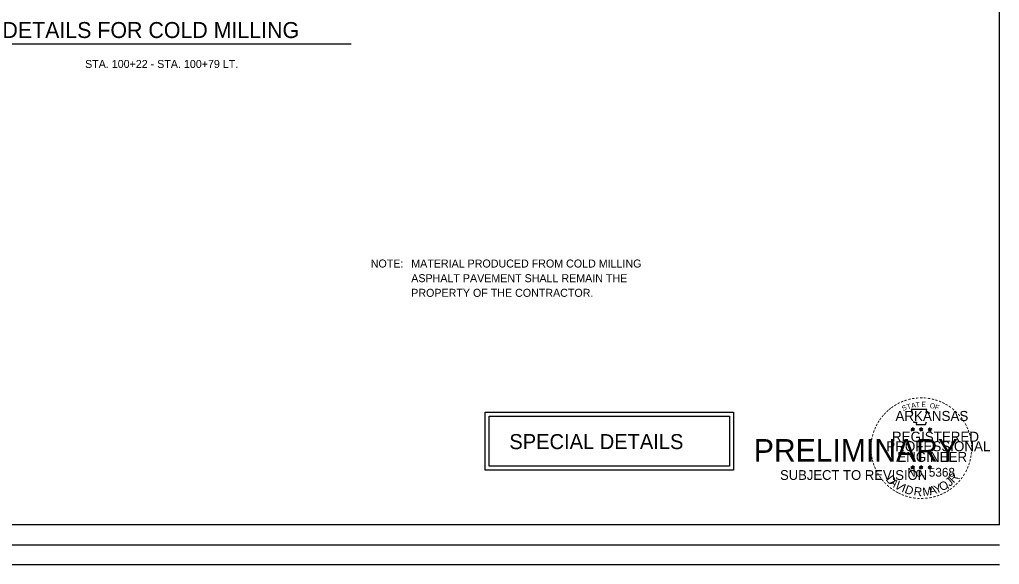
# Model space of a CAD drawing. Extents: x 1944905 to 1956777, y 763871 to 764977.
# Drawn here: x 1954088 to 1955068, y 763871 to 764415 of the extents above; entities that cross this region are included whole.
import ezdxf

# ---------------------------------------------------------------- set-up
doc = ezdxf.new("R2010")
doc.units = 0
for name, color, linetype in [('Default', 7, 'Continuous'), ('R_Border PE', 7, 'Continuous'), ('R_Dimension', 7, 'Continuous')]:
    doc.layers.add(name, color=color, linetype=linetype)

msp = doc.modelspace()

# ---------------------------------------------------------------- linework, layer by layer
at = {"layer": 'Default'}
for p, q in [((1955067.69, 763910.07), (1955067.69, 764937.29)), ((1955067.69, 763910.07), (1953486.78, 763910.07)), ((1953453.94, 763890.36), (1955067.69, 763890.36)), ((1953453.94, 763870.67), (1955067.69, 763870.67))]:
    msp.add_line(p, q, dxfattribs=at)
for points in [[(1954553.78, 764022.9), (1954801.79, 764022.9), (1954801.79, 763964.87), (1954553.78, 763964.87)], [(1954557.78, 764018.9), (1954797.79, 764018.9), (1954797.79, 763968.87), (1954557.78, 763968.87)]]:
    msp.add_lwpolyline(points, close=True, dxfattribs=at)
at = {"layer": 'R_Border PE'}
for p, q in [((1954979.35, 764006.04), (1954981.05, 764005.49)), ((1954979.35, 764006.04), (1954980.6, 764005.89)), ((1954979.35, 764006.04), (1954980.6, 764005.84)), ((1954979.35, 764006.04), (1954980.55, 764005.74)), ((1954979.35, 764006.04), (1954980.55, 764005.54)), ((1954979.35, 764006.04), (1954980.5, 764005.44)), ((1954979.35, 764006.04), (1954980.5, 764005.34)), ((1954981.05, 764007.29), (1954980.8, 764006.09)), ((1954981.05, 764007.29), (1954980.85, 764006.04)), ((1954981.05, 764007.29), (1954981, 764006.04)), ((1954981.05, 764005.49), (1954981.05, 764007.29)), ((1954981.05, 764007.29), (1954981.4, 764006.04)), ((1954981.05, 764007.29), (1954981.3, 764006.04)), ((1954981.05, 764007.29), (1954981.2, 764006.09)), ((1954982.8, 764006.04), (1954981.05, 764005.49)), ((1954982.8, 764006.04), (1954981.3, 764005.94)), ((1954982.8, 764006.04), (1954981.4, 764005.79)), ((1954982.8, 764006.04), (1954981.4, 764005.69)), ((1954982.8, 764006.04), (1954981.7, 764005.59)), ((1954982.8, 764006.04), (1954981.8, 764005.54)), ((1954982.8, 764006.04), (1954981.85, 764005.49)), ((1954987.65, 764006.04), (1954989.4, 764005.49)), ((1954987.65, 764006.04), (1954988.95, 764005.89)), ((1954987.65, 764006.04), (1954988.95, 764005.84)), ((1954987.65, 764006.04), (1954988.9, 764005.74)), ((1954987.65, 764006.04), (1954988.9, 764005.54)), ((1954987.65, 764006.04), (1954988.85, 764005.44)), ((1954987.65, 764006.04), (1954988.85, 764005.34)), ((1954989.4, 764007.29), (1954989.15, 764006.09)), ((1954989.4, 764007.29), (1954989.2, 764006.04)), ((1954989.4, 764007.29), (1954989.35, 764006.04)), ((1954989.4, 764005.49), (1954989.4, 764007.29)), ((1954989.4, 764007.29), (1954989.75, 764006.04)), ((1954989.4, 764007.29), (1954989.65, 764006.04)), ((1954989.4, 764007.29), (1954989.55, 764006.09)), ((1954991.15, 764006.04), (1954989.4, 764005.49)), ((1954991.15, 764006.04), (1954989.6, 764005.94)), ((1954991.15, 764006.04), (1954989.7, 764005.79)), ((1954991.15, 764006.04), (1954989.7, 764005.69)), ((1954991.15, 764006.04), (1954990.05, 764005.59)), ((1954991.15, 764006.04), (1954990.15, 764005.54)), ((1954991.15, 764006.04), (1954990.2, 764005.49)), ((1954996.5, 764005.99), (1954998.25, 764005.44)), ((1954996.5, 764005.99), (1954997.8, 764005.84)), ((1954996.5, 764005.99), (1954997.8, 764005.74)), ((1954996.5, 764005.99), (1954997.75, 764005.64)), ((1954996.5, 764005.99), (1954997.7, 764005.49)), ((1954996.5, 764005.99), (1954997.7, 764005.39)), ((1954996.5, 764005.99), (1954997.7, 764005.29)), ((1954998.25, 764007.24), (1954997.95, 764006.04)), ((1954998.25, 764007.24), (1954998.05, 764005.99)), ((1954998.25, 764007.24), (1954998.15, 764005.99)), ((1954998.25, 764005.44), (1954998.25, 764007.24)), ((1954998.25, 764007.24), (1954998.6, 764005.99)), ((1954998.25, 764007.24), (1954998.5, 764005.99)), ((1954998.25, 764007.24), (1954998.35, 764006.04)), ((1955000, 764005.99), (1954998.25, 764005.44)), ((1955000, 764005.99), (1954998.45, 764005.89)), ((1955000, 764005.99), (1954998.55, 764005.74)), ((1955000, 764005.99), (1954998.55, 764005.64)), ((1955000, 764005.99), (1954998.9, 764005.54)), ((1955000, 764005.99), (1954998.95, 764005.49)), ((1955000, 764005.99), (1954999.05, 764005.44)), ((1954980, 764003.99), (1954981.05, 764005.49)), ((1954980, 764003.99), (1954980.55, 764005.39)), ((1954980, 764003.99), (1954980.6, 764005.24)), ((1954980, 764003.99), (1954980.7, 764005.19)), ((1954980, 764003.99), (1954981.05, 764005.09)), ((1954980, 764003.99), (1954980.85, 764005.04)), ((1954980, 764003.99), (1954981.1, 764004.94)), ((1954982.15, 764003.99), (1954981.05, 764005.49)), ((1954982.15, 764003.99), (1954981.05, 764005.09)), ((1954982.15, 764003.99), (1954981.05, 764004.94)), ((1954982.15, 764003.99), (1954981.25, 764005.04)), ((1954982.15, 764003.99), (1954981.4, 764005.24)), ((1954982.15, 764003.99), (1954981.45, 764005.44)), ((1954982.15, 764003.99), (1954981.55, 764005.44)), ((1954988.35, 764003.99), (1954989.4, 764005.49)), ((1954988.35, 764003.99), (1954988.9, 764005.39)), ((1954988.35, 764003.99), (1954988.95, 764005.24)), ((1954988.35, 764003.99), (1954989.05, 764005.19)), ((1954988.35, 764003.99), (1954989.4, 764005.09)), ((1954988.35, 764003.99), (1954989.2, 764005.04)), ((1954988.35, 764003.99), (1954989.45, 764004.94)), ((1954990.5, 764003.99), (1954989.4, 764005.49)), ((1954990.5, 764003.99), (1954989.4, 764005.09)), ((1954990.5, 764003.99), (1954989.4, 764004.94)), ((1954990.5, 764003.99), (1954989.6, 764005.04)), ((1954990.5, 764003.99), (1954989.75, 764005.24)), ((1954990.5, 764003.99), (1954989.8, 764005.44)), ((1954990.5, 764003.99), (1954989.9, 764005.44)), ((1954997.2, 764003.94), (1954998.25, 764005.44)), ((1954997.2, 764003.94), (1954997.75, 764005.34)), ((1954997.2, 764003.94), (1954997.8, 764005.14)), ((1954997.2, 764003.94), (1954997.9, 764005.14)), ((1954997.2, 764003.94), (1954998.25, 764005.04)), ((1954997.2, 764003.94), (1954998.05, 764004.99)), ((1954997.2, 764003.94), (1954998.3, 764004.89)), ((1954999.3, 764003.94), (1954998.25, 764005.44)), ((1954999.3, 764003.94), (1954998.25, 764005.04)), ((1954999.3, 764003.94), (1954998.25, 764004.89)), ((1954999.3, 764003.94), (1954998.45, 764004.99)), ((1954999.3, 764003.94), (1954998.6, 764005.19)), ((1954999.3, 764003.94), (1954998.65, 764005.39)), ((1954999.3, 764003.94), (1954998.75, 764005.39)), ((1954979.3, 763968.19), (1954981.05, 763967.64)), ((1954979.3, 763968.19), (1954980.6, 763968.04)), ((1954979.3, 763968.19), (1954980.6, 763967.94)), ((1954979.3, 763968.19), (1954980.55, 763967.84)), ((1954979.3, 763968.19), (1954980.5, 763967.69)), ((1954979.3, 763968.19), (1954980.5, 763967.59)), ((1954979.3, 763968.19), (1954980.5, 763967.44)), ((1954980, 763966.14), (1954981.05, 763967.64)), ((1954980, 763966.14), (1954980.55, 763967.54)), ((1954980, 763966.14), (1954980.6, 763967.34)), ((1954980, 763966.14), (1954980.7, 763967.29)), ((1954980, 763966.14), (1954981.05, 763967.24)), ((1954980, 763966.14), (1954980.85, 763967.19)), ((1954980, 763966.14), (1954981.1, 763967.09)), ((1954981.05, 763969.44), (1954980.75, 763968.24)), ((1954981.05, 763969.44), (1954980.85, 763968.19)), ((1954981.05, 763969.44), (1954980.95, 763968.19)), ((1954981.05, 763967.64), (1954981.05, 763969.44)), ((1954981.05, 763969.44), (1954981.4, 763968.19)), ((1954981.05, 763969.44), (1954981.3, 763968.19)), ((1954981.05, 763969.44), (1954981.15, 763968.19)), ((1954982.8, 763968.19), (1954981.05, 763967.64)), ((1954982.1, 763966.14), (1954981.05, 763967.64)), ((1954982.1, 763966.14), (1954981.05, 763967.19)), ((1954982.1, 763966.14), (1954981.05, 763967.09)), ((1954982.8, 763968.19), (1954981.25, 763968.09)), ((1954982.1, 763966.14), (1954981.25, 763967.19)), ((1954982.8, 763968.19), (1954981.35, 763967.94)), ((1954982.8, 763968.19), (1954981.35, 763967.84)), ((1954982.1, 763966.14), (1954981.4, 763967.34)), ((1954982.1, 763966.14), (1954981.45, 763967.59)), ((1954982.1, 763966.14), (1954981.55, 763967.59)), ((1954982.8, 763968.19), (1954981.7, 763967.74)), ((1954982.8, 763968.19), (1954981.75, 763967.69)), ((1954982.8, 763968.19), (1954981.85, 763967.59)), ((1954987.65, 763968.19), (1954989.4, 763967.64)), ((1954987.65, 763968.19), (1954988.95, 763968.04)), ((1954987.65, 763968.19), (1954988.9, 763967.94)), ((1954987.65, 763968.19), (1954988.9, 763967.84)), ((1954987.65, 763968.19), (1954988.85, 763967.69)), ((1954987.65, 763968.19), (1954988.85, 763967.59)), ((1954987.65, 763968.19), (1954988.85, 763967.44)), ((1954988.3, 763966.14), (1954989.4, 763967.64)), ((1954988.3, 763966.14), (1954988.9, 763967.54)), ((1954988.3, 763966.14), (1954988.95, 763967.34)), ((1954988.3, 763966.14), (1954989.05, 763967.29)), ((1954988.3, 763966.14), (1954989.4, 763967.24)), ((1954988.3, 763966.14), (1954989.2, 763967.19)), ((1954988.3, 763966.14), (1954989.4, 763967.09)), ((1954989.4, 763969.44), (1954989.1, 763968.24)), ((1954989.4, 763969.44), (1954989.2, 763968.19)), ((1954989.4, 763969.44), (1954989.3, 763968.19)), ((1954989.4, 763967.64), (1954989.4, 763969.44)), ((1954989.4, 763969.44), (1954989.75, 763968.19)), ((1954989.4, 763969.44), (1954989.65, 763968.19)), ((1954989.4, 763969.44), (1954989.5, 763968.19)), ((1954991.15, 763968.19), (1954989.4, 763967.64)), ((1954990.45, 763966.14), (1954989.4, 763967.64)), ((1954990.45, 763966.14), (1954989.4, 763967.19)), ((1954990.45, 763966.14), (1954989.4, 763967.09)), ((1954991.15, 763968.19), (1954989.6, 763968.09)), ((1954990.45, 763966.14), (1954989.6, 763967.19)), ((1954991.15, 763968.19), (1954989.7, 763967.94)), ((1954991.15, 763968.19), (1954989.7, 763967.84)), ((1954990.45, 763966.14), (1954989.75, 763967.34)), ((1954990.45, 763966.14), (1954989.8, 763967.59)), ((1954990.45, 763966.14), (1954989.9, 763967.59)), ((1954991.15, 763968.19), (1954990, 763967.74)), ((1954991.15, 763968.19), (1954990.1, 763967.69)), ((1954991.15, 763968.19), (1954990.2, 763967.59)), ((1954996.5, 763968.14), (1954998.25, 763967.54)), ((1954996.5, 763968.14), (1954997.75, 763967.99)), ((1954996.5, 763968.14), (1954997.75, 763967.89)), ((1954996.5, 763968.14), (1954997.7, 763967.79)), ((1954996.5, 763968.14), (1954997.7, 763967.64)), ((1954996.5, 763968.14), (1954997.65, 763967.49)), ((1954996.5, 763968.14), (1954997.65, 763967.39)), ((1954997.15, 763966.09), (1954998.25, 763967.54)), ((1954997.15, 763966.09), (1954997.7, 763967.44)), ((1954997.15, 763966.09), (1954997.8, 763967.29)), ((1954997.15, 763966.09), (1954997.9, 763967.24)), ((1954997.15, 763966.09), (1954998.05, 763967.14)), ((1954997.15, 763966.09), (1954998.2, 763967.14)), ((1954997.15, 763966.09), (1954998.25, 763967.04)), ((1954998.25, 763969.39), (1954997.95, 763968.14)), ((1954998.25, 763969.39), (1954998.05, 763968.14)), ((1954998.25, 763969.39), (1954998.15, 763968.14)), ((1954999.3, 763966.09), (1954998.2, 763967.14)), ((1954999.3, 763966.09), (1954998.2, 763966.99)), ((1954998.25, 763967.54), (1954998.25, 763969.39)), ((1954998.25, 763969.39), (1954998.55, 763968.14)), ((1954998.25, 763969.39), (1954998.5, 763968.14)), ((1954998.25, 763969.39), (1954998.35, 763968.14)), ((1954999.95, 763968.14), (1954998.25, 763967.54)), ((1954999.3, 763966.09), (1954998.25, 763967.54)), ((1954999.3, 763966.09), (1954998.4, 763967.14)), ((1954999.95, 763968.14), (1954998.45, 763967.99)), ((1954999.95, 763968.14), (1954998.55, 763967.89)), ((1954999.95, 763968.14), (1954998.55, 763967.79)), ((1954999.3, 763966.09), (1954998.6, 763967.54)), ((1954999.3, 763966.09), (1954998.6, 763967.29)), ((1954999.3, 763966.09), (1954998.75, 763967.54)), ((1954999.95, 763968.14), (1954998.85, 763967.64)), ((1954999.95, 763968.14), (1954998.95, 763967.59)), ((1954999.95, 763968.14), (1954999, 763967.54))]:
    msp.add_line(p, q, dxfattribs=at)
for points in [[(1954979.55, 764025.44), (1954980.9, 764021.29)], [(1954997.1, 764020.84), (1954997.8, 764022.24), (1954994.35, 764022.14), (1954995.1, 764025.44), (1954979.55, 764025.44)], [(1954981.05, 764007.29), (1954982.15, 764003.99), (1954979.35, 764006.04), (1954982.8, 764006.04), (1954980, 764003.99), (1954981.05, 764007.29)], [(1954982, 764013.34), (1954982, 764012.89), (1954984.8, 764012.79), (1954984.55, 764010.44), (1954993.9, 764010.44), (1954994.9, 764013.09)], [(1954989.4, 764007.29), (1954990.5, 764003.99), (1954987.65, 764006.04), (1954991.15, 764006.04), (1954988.35, 764003.99), (1954989.4, 764007.29)], [(1954998.25, 764007.24), (1954999.3, 764003.94), (1954996.5, 764005.99), (1955000, 764005.99), (1954997.2, 764003.94), (1954998.25, 764007.24)], [(1954981.05, 763969.44), (1954982.1, 763966.14), (1954979.3, 763968.19), (1954982.8, 763968.19), (1954980, 763966.14), (1954981.05, 763969.44)], [(1954989.4, 763969.44), (1954990.45, 763966.14), (1954987.65, 763968.19), (1954991.15, 763968.19), (1954988.3, 763966.14), (1954989.4, 763969.44)], [(1954998.25, 763969.39), (1954999.3, 763966.09), (1954996.5, 763968.14), (1954999.95, 763968.14), (1954997.15, 763966.09), (1954998.25, 763969.39)]]:
    msp.add_lwpolyline(points, dxfattribs=at)
for centre, radius in [((1954981.05, 764005.49), 0.861), ((1954981.05, 764005.49), 0.78), ((1954981.05, 764005.49), 0.723), ((1954981.05, 764005.49), 0.664), ((1954981.05, 764005.49), 0.579), ((1954981.05, 764005.49), 0.537), ((1954981.05, 764005.49), 0.495), ((1954981.05, 764005.49), 0.426), ((1954981.05, 764005.49), 0.374), ((1954989.4, 764005.49), 0.861), ((1954989.4, 764005.49), 0.78), ((1954989.4, 764005.49), 0.723), ((1954989.4, 764005.49), 0.664), ((1954989.4, 764005.49), 0.579), ((1954989.4, 764005.49), 0.537), ((1954989.4, 764005.49), 0.495), ((1954989.4, 764005.49), 0.426), ((1954989.4, 764005.49), 0.374), ((1954998.23, 764005.43), 0.861), ((1954998.23, 764005.43), 0.78), ((1954998.23, 764005.43), 0.723), ((1954998.23, 764005.43), 0.664), ((1954998.23, 764005.43), 0.579), ((1954998.23, 764005.43), 0.537), ((1954998.23, 764005.43), 0.495), ((1954998.23, 764005.43), 0.426), ((1954981.05, 764005.49), 0.311), ((1954981.05, 764005.49), 0.248), ((1954981.05, 764005.49), 0.185), ((1954981.05, 764005.49), 0.148), ((1954981.05, 764005.49), 0.0721), ((1954989.4, 764005.49), 0.311), ((1954989.4, 764005.49), 0.248), ((1954989.4, 764005.49), 0.185), ((1954989.4, 764005.49), 0.148), ((1954989.4, 764005.49), 0.0721), ((1954998.23, 764005.43), 0.374), ((1954998.23, 764005.43), 0.311), ((1954998.23, 764005.43), 0.248), ((1954998.23, 764005.43), 0.185), ((1954998.23, 764005.43), 0.148), ((1954998.23, 764005.43), 0.0721), ((1954981.03, 763967.63), 0.861), ((1954981.03, 763967.63), 0.78), ((1954981.03, 763967.63), 0.723), ((1954981.03, 763967.63), 0.664), ((1954981.03, 763967.63), 0.579), ((1954981.03, 763967.63), 0.537), ((1954981.03, 763967.63), 0.495), ((1954981.03, 763967.63), 0.426), ((1954981.03, 763967.63), 0.374), ((1954981.03, 763967.63), 0.311), ((1954981.03, 763967.63), 0.248), ((1954981.03, 763967.63), 0.185), ((1954981.03, 763967.63), 0.148), ((1954981.03, 763967.63), 0.0721), ((1954989.38, 763967.63), 0.861), ((1954989.38, 763967.63), 0.78), ((1954989.38, 763967.63), 0.723), ((1954989.38, 763967.63), 0.664), ((1954989.38, 763967.63), 0.579), ((1954989.38, 763967.63), 0.537), ((1954989.38, 763967.63), 0.495), ((1954989.38, 763967.63), 0.426), ((1954989.38, 763967.63), 0.374), ((1954989.38, 763967.63), 0.311), ((1954989.38, 763967.63), 0.248), ((1954989.38, 763967.63), 0.185), ((1954989.38, 763967.63), 0.148), ((1954989.38, 763967.63), 0.0721), ((1954998.21, 763967.57), 0.861), ((1954998.21, 763967.57), 0.78), ((1954998.21, 763967.57), 0.723), ((1954998.21, 763967.57), 0.664), ((1954998.21, 763967.57), 0.579), ((1954998.21, 763967.57), 0.537), ((1954998.21, 763967.57), 0.495), ((1954998.21, 763967.57), 0.426), ((1954998.21, 763967.57), 0.374), ((1954998.21, 763967.57), 0.311), ((1954998.21, 763967.57), 0.248), ((1954998.21, 763967.57), 0.185), ((1954998.21, 763967.57), 0.148), ((1954998.21, 763967.57), 0.0721)]:
    msp.add_circle(centre, radius, dxfattribs=at)
at = {"layer": 'R_Dimension'}
msp.add_line((1954072.84, 764390.69), (1954419.87, 764390.69), dxfattribs=at)

# ---------------------------------------------------------------- texts
at = {"layer": 'Default'}
for s, height, p in [('SPECIAL DETAILS', 15, (1954577.97, 763985.86)), ('PRELIMINARY', 22.5, (1954822.28, 763973.37)), ('        SUBJECT TO REVISION', 9.75, (1954819.46, 763955.1))]:
    msp.add_text(s, height=height, dxfattribs=at).set_placement(p)
at = {"layer": 'R_Border PE'}
for s, height, rotation, p in [('-', 8, 19.17608, (1954973.25, 764031.09)), ('-', 8, 13.63015, (1954977, 764032.29)), ('-', 8, 10.21935, (1954980.4, 764033.09)), ('-', 8, 5.89682, (1954984.05, 764033.64)), ('-', 8, 0.18623, (1954987.9, 764033.99)), ('-', 8, 357.74304, (1954991.55, 764033.94)), ('-', 8, 352.16173, (1954995.25, 764033.64)), ('-', 8, 347.20489, (1954998.85, 764033.09)), ('-', 8, 342.3362, (1955002, 764032.29)), ('-', 8, 38.95066, (1954958.7, 764022.44)), ('-', 8, 36.23174, (1954961.05, 764024.29)), ('-', 8, 34.06357, (1954963.95, 764026.29)), ('-', 8, 28.79182, (1954966.95, 764028.14)), ('-', 8, 24.30721, (1954970.1, 764029.74)), ('S', 5, 21.59401, (1954971.3, 764023.84)), ('T', 5, 16.4036, (1954975.9, 764025.49)), ('A', 5, 11.21318, (1954980, 764026.74)), ('T', 5, 6.02276, (1954984.25, 764027.54)), ('E', 5, 0.83234, (1954989.8, 764028.09)), ('O', 5, 350.4515, (1954997.8, 764027.04)), ('F', 5, 340.07066, (1955002.55, 764025.94)), ('-', 8, 337.85509, (1955005.7, 764031.19)), ('-', 8, 334.12109, (1955008.85, 764029.84)), ('-', 8, 329.64089, (1955011.75, 764028.44)), ('-', 8, 325.86266, (1955014.95, 764026.59)), ('-', 8, 320.52971, (1955018, 764024.49)), ('-', 8, 54.23247, (1954950.2, 764012.69)), ('-', 8, 50.61417, (1954952.25, 764015.54)), ('-', 8, 48.42305, (1954954.3, 764017.94)), ('-', 8, 42.96224, (1954956.5, 764020.34)), ('-', 8, 315.57859, (1955021, 764022.04)), ('-', 8, 309.87973, (1955023.85, 764019.29)), ('-', 8, 306.65218, (1955026.5, 764016.29)), ('-', 8, 67.77427, (1954945.7, 764003.94)), ('-', 8, 62.87135, (1954947, 764006.99)), ('-', 8, 58.07063, (1954948.55, 764010.04)), ('-', 7, 303.67529, (1955028.9, 764013.44)), ('-', 8, 299.66835, (1955030.5, 764010.39)), ('-', 8, 294.66279, (1955032.1, 764007.34)), ('-', 8, 81.20126, (1954942.95, 763993.64)), ('-', 8, 75.46096, (1954943.65, 763997.19)), ('-', 8, 72.39447, (1954944.6, 764000.79)), ('-', 8, 290.57283, (1955033.4, 764004.44)), ('-', 8, 285.12326, (1955034.6, 764001.54)), ('-', 8, 280.54934, (1955035.6, 763997.84)), ('-', 8, 89.06224, (1954942.45, 763986.69)), ('-', 8, 85.18634, (1954942.6, 763990.19)), ('-', 8, 276.59616, (1955036.4, 763993.99)), ('-', 8, 274.33011, (1955036.7, 763990.39)), ('-', 8, 269.94067, (1955036.85, 763987.24)), ('-', 8, 94.19588, (1954942.65, 763983.04)), ('-', 8, 98.94793, (1954943, 763979.74)), ('-', 8, 101.71495, (1954943.7, 763976.04)), ('-', 8, 260.99529, (1955036.4, 763980.64)), ('-', 8, 263.5172, (1955036.75, 763983.89)), ('-', 8, 105.45785, (1954944.5, 763973.09)), ('-', 8, 109.08742, (1954945.55, 763969.94)), ('-', 8, 114.06432, (1954946.85, 763966.94)), ('-', 8, 247.88866, (1955033.85, 763970.29)), ('-', 8, 252.86809, (1955034.95, 763973.64)), ('-', 8, 255.7626, (1955035.85, 763977.24)), ('-', 8, 115.72885, (1954948.35, 763963.84)), ('-', 8, 120.44712, (1954950.15, 763960.94)), ('-', 8, 125.89344, (1954952.15, 763958.14)), ('D', 8.47, 308.02669, (1954953.7, 763955.44)), ('J', 8.47, 40.15065, (1955018.05, 763948.09)), ('R', 8.47, 46.29225, (1955021.8, 763951.44)), ('-', 8, 233.84524, (1955028.55, 763960.14)), ('-', 8, 239.07125, (1955030.55, 763963.39)), ('-', 8, 244.61971, (1955032.55, 763967.14)), ('-', 8, 130.71812, (1954954.45, 763955.34)), ('-', 8, 134.22381, (1954957.05, 763952.64)), ('-', 8, 138.93382, (1954959.7, 763950.29)), ('A', 7.7, 314.16829, (1954957.45, 763951.99)), ('-', 8, 144.64634, (1954962.45, 763948.29)), ('V', 8.47, 322.07513, (1954962.1, 763947.94)), ('ID', 8.47, 339.24466, (1954969.35, 763943.49)), ('R', 8.47, 351.48461, (1954981.65, 763939.94)), ('M', 8.47, 7.38422, (1954991.35, 763938.79)), ('A', 8.47, 15.04444, (1954998.35, 763939.74)), ('Y', 8.47, 21.72586, (1955004.15, 763941.09)), ('O', 8.47, 27.86746, (1955010.05, 763943.49)), (',', 8.45, 13.66842, (1955014.9, 763946.74)), ('-', 8, 215.73633, (1955018.65, 763949.54)), ('-', 8, 221.08509, (1955021.4, 763951.94)), ('-', 8, 225.76533, (1955024, 763954.49)), ('-', 8, 231.25377, (1955026.4, 763957.29)), ('-', 8, 148.08978, (1954965.25, 763946.44)), ('-', 8, 151.57039, (1954968.15, 763944.79)), ('-', 8, 154.60019, (1954970.75, 763943.59)), ('-', 8, 158.56121, (1954973.9, 763942.29)), ('-', 8, 162.79826, (1954977.3, 763941.24)), ('-', 8, 167.55551, (1954980.9, 763940.39)), ('-', 8, 173.11546, (1954984.75, 763939.84)), ('.', 7.7, 351.01787, (1954987.45, 763938.99)), ('-', 8, 185.81666, (1954996.25, 763940.09)), ('-', 8, 191.28576, (1954999.95, 763940.74)), ('-', 8, 195.47429, (1955003.6, 763941.74)), ('-', 8, 200.71842, (1955006.95, 763942.94)), ('-', 8, 204.25161, (1955010.05, 763944.29)), ('-', 8, 207.35684, (1955013.2, 763945.89)), ('-', 8, 212.24909, (1955016, 763947.64)), ('-', 8, 176.51827, (1954988.5, 763939.59)), ('-', 8, 181.59176, (1954992.2, 763939.69))]:
    msp.add_text(s, height=height, rotation=rotation, dxfattribs=at).set_placement(p)
for s, height, p in [('ARKANSAS', 10, (1954963.8, 764013.99)), ('REGISTERED', 10, (1954960.4, 763993.24)), ('PROFESSIONAL', 9.9999, (1954954.65, 763983.74)), ('ENGINEER', 10, (1954965.6, 763973.09)), ('No. 5368', 8.785, (1954975.6, 763958.34)), ('.', 8.45, (1955025.85, 763955.84))]:
    msp.add_text(s, height=height, dxfattribs=at).set_placement(p)
at = {"layer": 'R_Dimension'}
for s, height, p in [('DETAILS FOR COLD MILLING', 15.963, (1954071.33, 764396.6)), ('STA. 100+22 - STA. 100+79 LT.', 7.9815, (1954153.92, 764366.7)), ('NOTE: ', 7.982, (1954439.43, 764167.29)), ('MATERIAL PRODUCED FROM COLD MILLING', 7.9815, (1954479.9, 764167.29)), ('ASPHALT PAVEMENT SHALL REMAIN THE', 7.9815, (1954479.9, 764152.66)), ('PROPERTY OF THE CONTRACTOR.', 7.9815, (1954479.9, 764138.03))]:
    msp.add_text(s, height=height, dxfattribs=at).set_placement(p)

doc.saveas('drawing.dxf')
